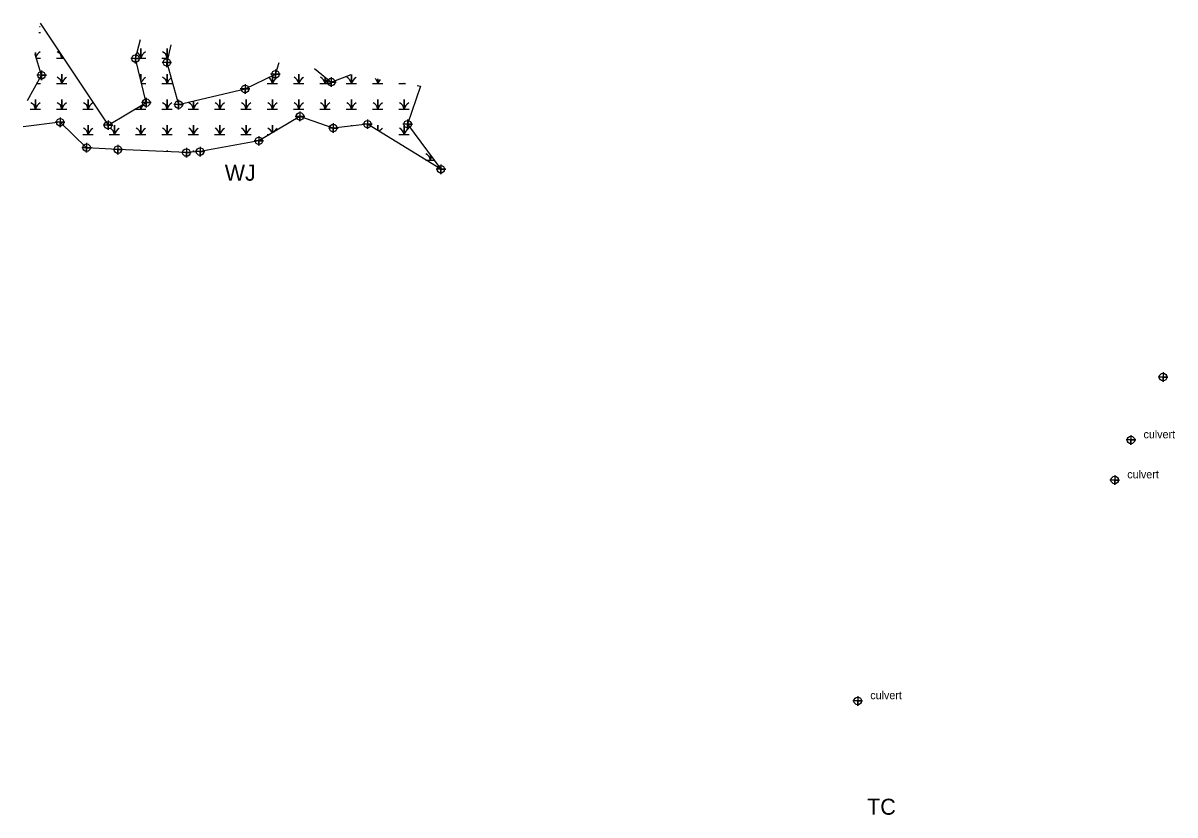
# Model space of a CAD drawing. Extents: x 2174810 to 2196950, y 76168 to 88270.
# Drawn here: x 2190985 to 2191705, y 86793 to 87288 of the extents above; entities that cross this region are included whole.
import ezdxf

# ---------------------------------------------------------------- set-up
doc = ezdxf.new("R2010")
doc.units = 0
for name, color, linetype in [('Exist Environmental Wetland Boundary', 7, 'Continuous'), ('Exist Environmental Wetland Boundary Cogo Point CELL', 7, 'Continuous'), ('Exist Environmental Wetland Boundary Text', 7, 'Continuous'), ('Exist Hydro Jurisdictional Stream or Body of Water NonMitigable Cogo Number', 7, 'Continuous'), ('Exist Hydro Jurisdictional Stream or Body of Water NonMitigable Cogo Point CELL', 7, 'Continuous'), ('Exist Hydro Jurisdictional Stream or Body of Water NonMitigable Text', 7, 'Continuous'), ('Exist Hydro Swamp or Marsh', 7, 'Continuous')]:
    doc.layers.add(name, color=color, linetype=linetype)

msp = doc.modelspace()

# ---------------------------------------------------------------- linework, layer by layer
at = {"layer": 'Exist Environmental Wetland Boundary'}
for points in [[(2190995.69, 87287.91), (2191038.08, 87224.12), (2191061.93, 87238.18), (2191055.2, 87265.7), (2191058.23, 87277.55)], [(2191077.33, 87274.38), (2191074.77, 87263.25), (2191082.11, 87236.96), (2191123.69, 87246.74), (2191142.65, 87255.91), (2191144.87, 87263.19)], [(2190987.68, 87239.55), (2190996.49, 87255.3), (2190992.43, 87268.22)], [(2191167.1, 87259.5), (2191177.5, 87251.02), (2191189.93, 87255.72)], [(2191231.25, 87248.87), (2191233.34, 87248.52), (2191225.2, 87224.73), (2191245.99, 87196.6), (2191200.13, 87224.73), (2191178.73, 87222.28), (2191157.93, 87229.62), (2191132.25, 87214.33), (2191095.56, 87207.6), (2191087, 87206.99), (2191044.19, 87208.83), (2191024.62, 87210.05), (2191008.11, 87225.95), (2190984.93, 87222.98)]]:
    msp.add_lwpolyline(points, dxfattribs=at)
at = {"layer": 'Exist Environmental Wetland Boundary Cogo Point CELL'}
for points in [[(2191055.2, 87268.7), (2191055.2, 87262.7), (2191055.2, 87265.7), (2191058.2, 87265.7), (2191052.2, 87265.7)], [(2191074.77, 87266.25), (2191074.77, 87260.25), (2191074.77, 87263.25), (2191077.77, 87263.25), (2191071.77, 87263.25)], [(2190996.49, 87258.3), (2190996.49, 87252.3), (2190996.49, 87255.3), (2190999.49, 87255.3), (2190993.49, 87255.3)], [(2191142.65, 87258.91), (2191142.65, 87252.91), (2191142.65, 87255.91), (2191145.65, 87255.91), (2191139.65, 87255.91)], [(2191177.5, 87254.02), (2191177.5, 87248.02), (2191177.5, 87251.02), (2191180.5, 87251.02), (2191174.5, 87251.02)], [(2191123.69, 87249.74), (2191123.69, 87243.74), (2191123.69, 87246.74), (2191126.69, 87246.74), (2191120.69, 87246.74)], [(2191061.93, 87241.18), (2191061.93, 87235.18), (2191061.93, 87238.18), (2191064.93, 87238.18), (2191058.93, 87238.18)], [(2191082.11, 87239.96), (2191082.11, 87233.96), (2191082.11, 87236.96), (2191085.11, 87236.96), (2191079.11, 87236.96)], [(2191157.93, 87232.62), (2191157.93, 87226.62), (2191157.93, 87229.62), (2191160.93, 87229.62), (2191154.93, 87229.62)], [(2191008.11, 87228.95), (2191008.11, 87222.95), (2191008.11, 87225.95), (2191011.11, 87225.95), (2191005.11, 87225.95)], [(2191038.08, 87227.12), (2191038.08, 87221.12), (2191038.08, 87224.12), (2191041.08, 87224.12), (2191035.08, 87224.12)], [(2191178.73, 87225.28), (2191178.73, 87219.28), (2191178.73, 87222.28), (2191181.73, 87222.28), (2191175.73, 87222.28)], [(2191200.13, 87227.73), (2191200.13, 87221.73), (2191200.13, 87224.73), (2191203.13, 87224.73), (2191197.13, 87224.73)], [(2191225.2, 87227.73), (2191225.2, 87221.73), (2191225.2, 87224.73), (2191228.2, 87224.73), (2191222.2, 87224.73)], [(2191132.25, 87217.33), (2191132.25, 87211.33), (2191132.25, 87214.33), (2191135.25, 87214.33), (2191129.25, 87214.33)], [(2191024.62, 87213.05), (2191024.62, 87207.05), (2191024.62, 87210.05), (2191027.62, 87210.05), (2191021.62, 87210.05)], [(2191044.19, 87211.83), (2191044.19, 87205.83), (2191044.19, 87208.83), (2191047.19, 87208.83), (2191041.19, 87208.83)], [(2191087, 87209.99), (2191087, 87203.99), (2191087, 87206.99), (2191090, 87206.99), (2191084, 87206.99)], [(2191095.56, 87210.6), (2191095.56, 87204.6), (2191095.56, 87207.6), (2191098.56, 87207.6), (2191092.56, 87207.6)], [(2191245.99, 87199.6), (2191245.99, 87193.6), (2191245.99, 87196.6), (2191248.99, 87196.6), (2191242.99, 87196.6)]]:
    msp.add_lwpolyline(points, dxfattribs=at)
for centre in [(2191055.2, 87265.7), (2191074.77, 87263.25), (2191142.65, 87255.91), (2190996.49, 87255.3), (2191177.5, 87251.02), (2191123.69, 87246.74), (2191061.93, 87238.18), (2191082.11, 87236.96), (2191157.93, 87229.62), (2191008.11, 87225.95), (2191038.08, 87224.12), (2191178.73, 87222.28), (2191200.13, 87224.73), (2191225.2, 87224.73), (2191132.25, 87214.33), (2191024.62, 87210.05), (2191044.19, 87208.83), (2191087, 87206.99), (2191095.56, 87207.6), (2191245.99, 87196.6)]:
    msp.add_circle(centre, 2.34, dxfattribs=at)
at = {"layer": 'Exist Hydro Jurisdictional Stream or Body of Water NonMitigable Cogo Point CELL'}
for points in [[(2191697.2, 87069.78), (2191697.2, 87063.78), (2191697.2, 87066.78), (2191700.2, 87066.78), (2191694.2, 87066.78)], [(2191677.15, 87030.46), (2191677.15, 87024.46), (2191677.15, 87027.46), (2191680.15, 87027.46), (2191674.15, 87027.46)], [(2191666.99, 87005.46), (2191666.99, 86999.46), (2191666.99, 87002.46), (2191669.99, 87002.46), (2191663.99, 87002.46)], [(2191506.45, 86867.46), (2191506.45, 86861.46), (2191506.45, 86864.46), (2191509.45, 86864.46), (2191503.45, 86864.46)]]:
    msp.add_lwpolyline(points, dxfattribs=at)
for centre in [(2191697.2, 87066.78), (2191677.15, 87027.46), (2191666.99, 87002.46), (2191506.45, 86864.46)]:
    msp.add_circle(centre, 2.34, dxfattribs=at)
at = {"layer": 'Exist Hydro Swamp or Marsh'}
for p, q in [((2190994.7, 87281.92), (2190995.88, 87281.92)), ((2190992.65, 87267.52), (2190992.65, 87269.56)), ((2190992.65, 87269.56), (2190992.65, 87267.52)), ((2190993.13, 87266.01), (2190995.88, 87266.01)), ((2190993.58, 87250.09), (2190995.88, 87250.09)), ((2191059.02, 87250.09), (2191061.68, 87250.09)), ((2191137.49, 87218.25), (2191138.84, 87218.25))]:
    msp.add_line(p, q, dxfattribs=at)
for points in [[(2191005.88, 87266.01), (2191009.1, 87266.01), (2191009.1, 87267.72)], [(2191009.1, 87267.72), (2191009.1, 87266.01), (2191010.25, 87266.01)], [(2191055.28, 87266.01), (2191058.46, 87266.01), (2191058.46, 87271.92), (2191058.46, 87266.01), (2191061.68, 87266.01)], [(2191071.68, 87266.01), (2191074.91, 87266.01), (2191074.91, 87271.92), (2191074.91, 87266.01), (2191075.4, 87266.01)], [(2191005.88, 87250.09), (2191009.1, 87250.09), (2191009.1, 87256.01), (2191009.1, 87250.09), (2191012.33, 87250.09)], [(2191058.46, 87252.37), (2191058.46, 87256.01), (2191058.46, 87252.37)], [(2191071.68, 87250.09), (2191074.91, 87250.09), (2191074.91, 87256.01), (2191074.91, 87250.09), (2191078.14, 87250.09)], [(2191137.49, 87250.09), (2191140.71, 87250.09), (2191140.71, 87254.98)], [(2191140.71, 87254.98), (2191140.71, 87250.09), (2191143.94, 87250.09)], [(2191153.94, 87250.09), (2191157.17, 87250.09), (2191157.17, 87256.01), (2191157.17, 87250.09), (2191160.39, 87250.09)], [(2191170.39, 87250.09), (2191173.62, 87250.09), (2191173.62, 87254.19)], [(2191173.62, 87254.19), (2191173.62, 87250.09), (2191176.84, 87250.09)], [(2191186.84, 87250.09), (2191190.07, 87250.09), (2191190.07, 87255.7)], [(2191190.07, 87255.7), (2191190.07, 87250.09), (2191193.29, 87250.09)], [(2191203.29, 87250.09), (2191206.52, 87250.09), (2191206.52, 87252.97)], [(2191206.52, 87252.97), (2191206.52, 87250.09), (2191209.74, 87250.09)], [(2191219.74, 87250.09), (2191222.97, 87250.09), (2191222.97, 87250.24)], [(2191222.97, 87250.24), (2191222.97, 87250.09), (2191223.91, 87250.09)], [(2190989.43, 87234.17), (2190992.65, 87234.17), (2190992.65, 87240.09), (2190992.65, 87234.17), (2190995.88, 87234.17)], [(2191005.88, 87234.17), (2191009.1, 87234.17), (2191009.1, 87240.09), (2191009.1, 87234.17), (2191012.33, 87234.17)], [(2191022.33, 87234.17), (2191025.56, 87234.17), (2191025.56, 87240.09), (2191025.56, 87234.17), (2191028.78, 87234.17)], [(2191071.68, 87234.17), (2191074.91, 87234.17), (2191074.91, 87240.09), (2191074.91, 87234.17), (2191078.14, 87234.17)], [(2191088.14, 87234.17), (2191091.36, 87234.17), (2191091.36, 87239.13)], [(2191091.36, 87239.13), (2191091.36, 87234.17), (2191094.59, 87234.17)], [(2191104.59, 87234.17), (2191107.81, 87234.17), (2191107.81, 87240.09), (2191107.81, 87234.17), (2191111.04, 87234.17)], [(2191121.04, 87234.17), (2191124.26, 87234.17), (2191124.26, 87240.09), (2191124.26, 87234.17), (2191127.49, 87234.17)], [(2191137.49, 87234.17), (2191140.71, 87234.17), (2191140.71, 87240.09), (2191140.71, 87234.17), (2191143.94, 87234.17)], [(2191153.94, 87234.17), (2191157.17, 87234.17), (2191157.17, 87240.09), (2191157.17, 87234.17), (2191160.39, 87234.17)], [(2191170.39, 87234.17), (2191173.62, 87234.17), (2191173.62, 87240.09), (2191173.62, 87234.17), (2191176.84, 87234.17)], [(2191186.84, 87234.17), (2191190.07, 87234.17), (2191190.07, 87240.09), (2191190.07, 87234.17), (2191193.29, 87234.17)], [(2191203.29, 87234.17), (2191206.52, 87234.17), (2191206.52, 87240.09), (2191206.52, 87234.17), (2191209.74, 87234.17)], [(2191219.74, 87234.17), (2191222.97, 87234.17), (2191222.97, 87240.09), (2191222.97, 87234.17), (2191226.2, 87234.17)], [(2191055.23, 87234.17), (2191058.46, 87234.17), (2191058.46, 87236.13)], [(2191058.46, 87236.13), (2191058.46, 87234.17), (2191061.68, 87234.17)], [(2190992.65, 87223.97), (2190992.65, 87224.17), (2190992.65, 87223.97)], [(2191022.33, 87218.25), (2191025.56, 87218.25), (2191025.56, 87224.17), (2191025.56, 87218.25), (2191028.78, 87218.25)], [(2191038.78, 87218.25), (2191042.01, 87218.25), (2191042.01, 87224.17), (2191042.01, 87218.25), (2191045.23, 87218.25)], [(2191055.23, 87218.25), (2191058.46, 87218.25), (2191058.46, 87224.17), (2191058.46, 87218.25), (2191061.68, 87218.25)], [(2191071.68, 87218.25), (2191074.91, 87218.25), (2191074.91, 87224.17), (2191074.91, 87218.25), (2191078.14, 87218.25)], [(2191088.14, 87218.25), (2191091.36, 87218.25), (2191091.36, 87224.17), (2191091.36, 87218.25), (2191094.59, 87218.25)], [(2191104.59, 87218.25), (2191107.81, 87218.25), (2191107.81, 87224.17), (2191107.81, 87218.25), (2191111.04, 87218.25)], [(2191121.04, 87218.25), (2191124.26, 87218.25), (2191124.26, 87224.17), (2191124.26, 87218.25), (2191127.49, 87218.25)], [(2191140.71, 87219.37), (2191140.71, 87224.17), (2191140.71, 87219.37)], [(2191173.62, 87224.08), (2191173.62, 87224.17), (2191173.62, 87224.08)], [(2191190.07, 87223.58), (2191190.07, 87224.17), (2191190.07, 87223.58)], [(2191206.52, 87220.81), (2191206.52, 87224.17), (2191206.52, 87220.81)], [(2191219.74, 87218.25), (2191222.97, 87218.25), (2191222.97, 87224.17), (2191222.97, 87218.25), (2191226.2, 87218.25)], [(2191058.46, 87208.22), (2191058.46, 87208.25), (2191058.46, 87208.22)], [(2191074.91, 87207.51), (2191074.91, 87208.25), (2191074.91, 87207.51)], [(2191091.36, 87207.3), (2191091.36, 87208.25), (2191091.36, 87207.3)], [(2191236.64, 87202.33), (2191239.42, 87202.33), (2191239.42, 87205.49)], [(2191239.42, 87205.49), (2191239.42, 87202.33), (2191241.75, 87202.33)]]:
    msp.add_lwpolyline(points, dxfattribs=at)
for centre, radius, start, end in [((2190999.49, 87279.65), 7.21, 122.12745, 125.62013), ((2190999.49, 87263.73), 7.21, 122.12745, 155.85908), ((2191004.5, 87265.67), 4.61, 4.14034, 67.53497), ((2191015.95, 87263.73), 7.21, 152.54811, 161.62219), ((2191053.86, 87265.67), 4.61, 4.14034, 59.36749), ((2191065.3, 87263.73), 7.21, 122.12745, 161.62219), ((2191070.31, 87265.67), 4.61, 4.14034, 67.53497), ((2191081.75, 87263.73), 7.21, 145.34067, 161.62219), ((2191004.5, 87249.75), 4.61, 4.14034, 67.53497), ((2191015.95, 87247.81), 7.21, 122.12745, 161.62219), ((2191065.3, 87247.81), 7.21, 122.12745, 154.25673), ((2191070.31, 87249.75), 4.61, 4.14034, 67.53497), ((2191081.75, 87247.81), 7.21, 126.5267, 161.62219), ((2191136.11, 87249.75), 4.61, 4.14034, 61.65284), ((2191147.56, 87247.81), 7.21, 122.12745, 161.62219), ((2191152.57, 87249.75), 4.61, 4.14034, 67.53497), ((2191164.01, 87247.81), 7.21, 122.12745, 161.62219), ((2191169.02, 87249.75), 4.61, 4.14034, 67.53497), ((2191180.46, 87247.81), 7.21, 135.89206, 161.62219), ((2191185.47, 87249.75), 4.61, 4.14034, 67.53497), ((2191196.91, 87247.81), 7.21, 122.12745, 161.62219), ((2191201.92, 87249.75), 4.61, 4.14034, 48.89983), ((2191213.36, 87247.81), 7.21, 137.19731, 161.62219), ((2191218.37, 87249.75), 4.61, 4.14034, 6.11677), ((2191229.81, 87247.81), 7.21, 160.38088, 161.62219), ((2190988.05, 87233.84), 4.61, 4.14034, 67.53497), ((2190999.49, 87231.9), 7.21, 122.12745, 161.62219), ((2191004.5, 87233.84), 4.61, 4.14034, 67.53497), ((2191015.95, 87231.9), 7.21, 122.12745, 161.62219), ((2191020.96, 87233.84), 4.61, 4.14034, 67.53497), ((2191032.4, 87231.9), 7.21, 122.12745, 161.62219), ((2191065.3, 87231.9), 7.21, 129.23341, 161.62219), ((2191070.31, 87233.84), 4.61, 4.14034, 67.53497), ((2191081.75, 87231.9), 7.21, 122.12745, 161.62219), ((2191086.76, 87233.84), 4.61, 4.14034, 67.53497), ((2191098.2, 87231.9), 7.21, 122.12745, 161.62219), ((2191103.21, 87233.84), 4.61, 4.14034, 67.53497), ((2191114.65, 87231.9), 7.21, 122.12745, 161.62219), ((2191119.66, 87233.84), 4.61, 4.14034, 67.53497), ((2191131.1, 87231.9), 7.21, 122.12745, 161.62219), ((2191136.11, 87233.84), 4.61, 4.14034, 67.53497), ((2191147.56, 87231.9), 7.21, 122.12745, 161.62219), ((2191152.57, 87233.84), 4.61, 4.14034, 67.53497), ((2191164.01, 87231.9), 7.21, 122.12745, 161.62219), ((2191169.02, 87233.84), 4.61, 4.14034, 67.53497), ((2191180.46, 87231.9), 7.21, 122.12745, 161.62219), ((2191185.47, 87233.84), 4.61, 4.14034, 67.53497), ((2191196.91, 87231.9), 7.21, 122.12745, 161.62219), ((2191201.92, 87233.84), 4.61, 4.14034, 67.53497), ((2191213.36, 87231.9), 7.21, 122.12745, 161.62219), ((2191218.37, 87233.84), 4.61, 4.14034, 67.53497), ((2191229.81, 87231.9), 7.21, 122.12745, 161.62219), ((2191053.86, 87233.84), 4.61, 4.14034, 26.08952), ((2191020.96, 87217.92), 4.61, 4.14034, 67.53497), ((2191032.4, 87215.98), 7.21, 122.12745, 161.62219), ((2191037.41, 87217.92), 4.61, 4.14034, 67.53497), ((2191048.85, 87215.98), 7.21, 122.12745, 161.62219), ((2191053.86, 87217.92), 4.61, 4.14034, 67.53497), ((2191065.3, 87215.98), 7.21, 122.12745, 161.62219), ((2191070.31, 87217.92), 4.61, 4.14034, 67.53497), ((2191081.75, 87215.98), 7.21, 122.12745, 161.62219), ((2191086.76, 87217.92), 4.61, 4.14034, 67.53497), ((2191098.2, 87215.98), 7.21, 122.12745, 161.62219), ((2191103.21, 87217.92), 4.61, 4.14034, 67.53497), ((2191114.65, 87215.98), 7.21, 122.12745, 161.62219), ((2191119.66, 87217.92), 4.61, 4.14034, 67.53497), ((2191131.1, 87215.98), 7.21, 122.12745, 161.62219), ((2191136.11, 87217.92), 4.61, 16.88205, 67.53497), ((2191147.56, 87215.98), 7.21, 122.12745, 147.94907), ((2191213.36, 87215.98), 7.21, 122.12745, 144.19052), ((2191218.37, 87217.92), 4.61, 4.14034, 67.53497), ((2191229.81, 87215.98), 7.21, 122.12745, 161.62219), ((2191234.82, 87202), 4.61, 4.14034, 67.53497), ((2191246.26, 87200.06), 7.21, 144.8825, 161.62219)]:
    msp.add_arc(centre, radius, start, end, dxfattribs=at)

# ---------------------------------------------------------------- texts
at = {"layer": 'Exist Environmental Wetland Boundary Text'}
msp.add_text('WJ', height=10, dxfattribs=at).set_placement((2191111, 87189.41))
at = {"layer": 'Exist Hydro Jurisdictional Stream or Body of Water NonMitigable Cogo Number'}
for p in [(2191685, 87028.52), (2191674.85, 87003.52), (2191514.3, 86865.53)]:
    msp.add_text('culvert', height=5, dxfattribs=at).set_placement(p)
at = {"layer": 'Exist Hydro Jurisdictional Stream or Body of Water NonMitigable Text'}
msp.add_text('TC', height=10, dxfattribs=at).set_placement((2191512.37, 86793.37))

doc.saveas('drawing.dxf')
